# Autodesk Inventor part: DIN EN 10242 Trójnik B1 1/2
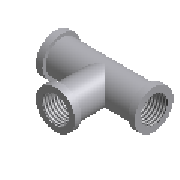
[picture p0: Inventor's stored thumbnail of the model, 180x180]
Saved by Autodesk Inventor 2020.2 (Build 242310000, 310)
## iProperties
Manager: www.cadconsulting.pl
Company: Fabian Stasiak CAD Consulting
IsCustomPart: 0
NAME: PIPING: DIN EN 10242 Tee B1
DATA: <meta><inlinegroups number="1" deflen="4.2"></inlinegroups><connections number="3"></connections><angles><a>3.14159265358979</a><a>1.57079632679489</a></angles>
Created: 2014-02
Part Number: DIN EN 10242 Trójnik B1 1/2
Material: Żelazo, ciągliwe
Description: Trójnik
Document SubType Name: Modeling
Standard: DIN EN 10242
Designer: F.Stasiak
Standards Organization: DIN
Language: pl-PL
Size Designation: 1/2
Categories: <MemberInstance><Categories><Category DisplayName="Rury cienko- i grubościenne" InternalName="4347fa0f-2144-441d-94cd-e3e15c92b736" Mnemonic="TUBEANDPIPE"><Cate
Density: 7.15 g/cm^3
Appearance: Częściowo polerowana
Catalog Web Link: www.expertbooks.pl
Author: F.Stasiak
Subject: Zbiór ćwiczeń. Autodesk Inventor 2020. Kurs Professional
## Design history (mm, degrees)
sketch "Sketch1"
  geometry: L1 (0, 0)-(56, 0); L2 (56, 0)-(56, 9.316); L3 (28, 0)-(28, 10.85); L4 (0, 0)-(0, 9.316); L5 (0, 9.316)-(13, 9.316); L6 (56, 9.316)-(43, 9.316); L7 (0, 9.316)-(0, 13.02); L8 (56, 9.316)-(56, 13.02); L9 (13, 9.316)-(43, 9.316); L10 (4.34, 10.85)-(51.66, 10.85); L11 (0, 13.02)-(4.34, 13.02); L12 (4.34, 13.02)-(4.34, 10.85); L13 (56, 13.02)-(51.66, 13.02); L14 (51.66, 13.02)-(51.66, 10.85); L15 (13, 9.316)-(13, 0); L16 (43, 9.316)-(43, 0)
  constraints: 32 end point, 5 perpendicular, 5 symmetric about line, 3 parallel, 2 horizontal, 2 midpoint, 2 point on line, 5 other
  dimensions: "d0" = 18.631 diameter of L4.end L1 (= MD); "d1" = 13 distance of L4.end L5.end (= a - z); "d2" = 28 distance between parallel lines of L3 L4 (= a); "d16" = 4.34 distance of L7.end L11.end (= EE); "d18" = 26.04 diameter of L11 L1 (= H); "d19" = 21.7 diameter of L10 L1 (= D)
revolve "Revolution1" sketch "Sketch1" stored, may be unused: angle "d8" = 90 deg
workplane "Work Plane1"
sketch "Sketch2"
  geometry: L1 (0, 0)-(56, 0) reference; L2 (28, 0)-(28, 10.85) reference; C1 r 10.85 at (28, 0); C2 r 9.316 at (28, 0); C3 r 13.02 at (28, 0)
  constraints: 3 centre point, 2 coincident, 2 concentric, 1 point on line
  dimensions: "d4" = 21.7 diameter of C1 (= D); "d6" = 18.631 diameter of C2 (= MD); "d20" = 26.04 diameter of C3 (= H)
extrude "Extrusion1" join sketch "Sketch2" taper "d5" = 0 deg; stored distance "d11" = 10
extrude "Extrusion2" join sketch "Sketch2" distance "d21" = 4.34 (= EE); taper "d22" = 0 deg
extrude "Extrusion3" cut sketch "Sketch2" taper "d7" = 0 deg; stored distance "d17" = 7.5 (= 0.5 x z)
sketch "Sketch3"
  geometry: L1 (0, 0)-(-56, 0) reference; L2 (-28, 0)-(-28, 15)
  constraints: 2 end point, 1 midpoint, 1 perpendicular
  dimensions: "d48" = 15 distance of L2.start L2.end (= z)
workpoint "Work Point1"
workpoint "Work Point2"
workpoint "Work Point3"
workaxis "Work Axis1"
workpoint "Work Point4"
workaxis "Work Axis2"
workpoint "Work Point5"
workaxis "Work Axis3"
workpoint "Work Point6"
body "Solid1"
feature "Gwint1" dims "d49" = 13 (= a - z), "d50" = 0
feature "Gwint2" dims "d51" = 13 (= a - z), "d52" = 0
feature "Gwint3" dims "d53" = 13 (= a - z), "d54" = 0
other parameters: "a" = 28 [user parameter; used in 6 equation terms], "D" = 21.7 [user parameter; used in 4 equation terms], "MD" = 18.631 [user parameter; used in 2 equation terms], "z" = 15 [user parameter; used in 6 equation terms], "d3" = 28 (= a), "H" = 26.04 (= 1.2 x D) [user parameter; used in 2 equation terms], "EE" = 4.34 (= 0.2 x D) [user parameter; used in 2 equation terms], "Size_Designation" = 5 [user parameter]
